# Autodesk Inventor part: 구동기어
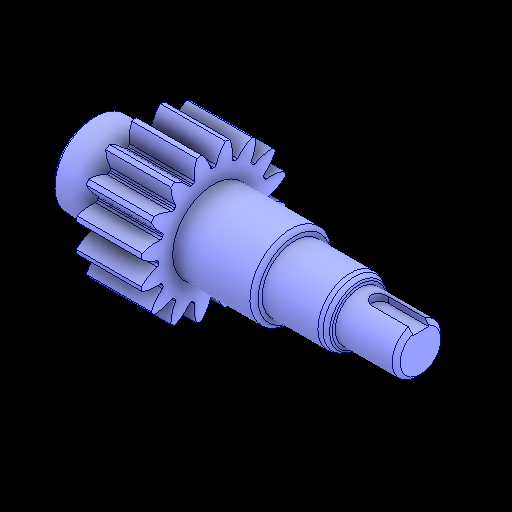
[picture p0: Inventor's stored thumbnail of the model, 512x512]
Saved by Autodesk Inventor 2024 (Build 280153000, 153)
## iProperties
Created: 2025-10
Part Number: 구동기어
Material: 강철, 합금
Document SubType Name: Modeling
Designer: EDU03
Density: 7.73 g/cm^3
Appearance: 기본값
Author: jhkim
Sending System: Autodesk Inventor 2026
Preprocessor: ST-DEVELOPER v20.1
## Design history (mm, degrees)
node "구동기어1"
node "솔리드2"
node "솔리드1"
